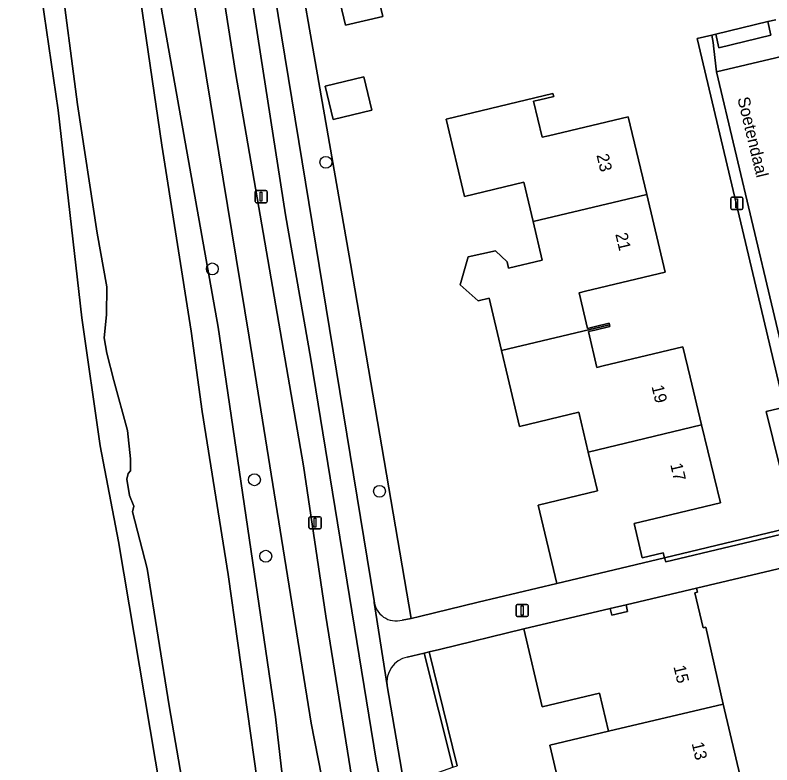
# Model space of a CAD drawing. Extents: x 157648 to 158502, y 379212 to 380938.
# Drawn here: x 158059.6 to 158121.9, y 380718.1 to 380779.8 of the extents above; entities that cross this region are included whole.
import ezdxf

# ---------------------------------------------------------------- set-up
doc = ezdxf.new("R2010")
doc.units = 0
for name, color, linetype in [('IMGEO_Berm_groen', 7, 'Continuous'), ('IMGEO_Boom', 7, 'Continuous'), ('IMGEO_Erf', 7, 'Continuous'), ('IMGEO_Fietspad_gesloten', 7, 'Continuous'), ('IMGEO_Groenvoorziening', 7, 'Continuous'), ('IMGEO_Haag', 7, 'Continuous'), ('IMGEO_Hek', 7, 'Continuous'), ('IMGEO_Lichtmast', 7, 'Continuous'), ('IMGEO_Muur', 7, 'Continuous'), ('IMGEO_Oever', 7, 'Continuous'), ('IMGEO_Openbare_ruimte_label', 7, 'Continuous'), ('IMGEO_Pand', 7, 'Continuous'), ('IMGEO_Pand_nummerreeks', 7, 'Continuous'), ('IMGEO_Pand_overbouw', 7, 'Continuous'), ('IMGEO_Rijbaan_lokaal_open', 7, 'Continuous'), ('IMGEO_Voetpad_open', 7, 'Continuous'), ('IMGEO_Waterloop', 7, 'Continuous')]:
    doc.layers.add(name, color=color, linetype=linetype)

msp = doc.modelspace()

# ---------------------------------------------------------------- linework, layer by layer
at = {"layer": 'IMGEO_Berm_groen'}
for points in [[(158074.722, 380845.281), (158073.77, 380825.588), (158073.53, 380817.736), (158073.74, 380808.222), (158074.257, 380799.995), (158075.149, 380791.663), (158077.752, 380775.038), (158083.324, 380742.71), (158085.161, 380730.364), (158087.771, 380714.145)], [(158086.247, 380709.967), (158083.967, 380721.558), (158078.875, 380753.293), (158072.85, 380789.952), (158072.183, 380797.022), (158071.547, 380810.292), (158071.664, 380824.995), (158072.408, 380844.132)], [(158090.58, 380712.063), (158089.326, 380718.53), (158083.93, 380751.483), (158081.843, 380763.329), (158076.731, 380796.337), (158076.033, 380804.062), (158075.551, 380812.413), (158075.894, 380824.951), (158076.565, 380843.437)], [(158072.443, 380710.798), (158068.133, 380736.496), (158066.607, 380744.346), (158065.118, 380754.866), (158063.151, 380771.932), (158061.06, 380786.446), (158059.17, 380797.604), (158058.451, 380809.187), (158058.445, 380817.028), (158058.623, 380823.199), (158058.845, 380827.656), (158058.831, 380835.186)], [(158069.5, 380835.023), (158068.853, 380822.132), (158068.821, 380815.256), (158068.663, 380810.855), (158070.02, 380791.954), (158071.648, 380780.25), (158076.307, 380754.118), (158081.044, 380722.078), (158082.383, 380710.401)]]:
    msp.add_lwpolyline(points, dxfattribs=at)
at = {"layer": 'IMGEO_Boom'}
for centre in [(158085.176, 380767.66), (158075.839, 380758.898), (158079.299, 380741.564), (158089.587, 380740.618), (158080.23, 380735.282)]:
    msp.add_circle(centre, 0.489, dxfattribs=at)
at = {"layer": 'IMGEO_Erf'}
for points in [[(158080.044, 380800.241), (158087.197, 380759.348), (158092.188, 380730.175), (158092.867, 380730.337), (158097.707, 380731.493), (158104.177, 380733.037), (158102.634, 380739.486), (158107.513, 380740.652), (158106.751, 380743.841), (158105.969, 380747.11), (158101.109, 380745.948), (158100.145, 380750), (158099.626, 380752.18), (158098.6, 380756.49), (158097.706, 380756.278), (158096.222, 380757.584), (158096.875, 380759.9), (158099.132, 380760.375), (158100.082, 380759.485), (158100.21, 380758.947), (158102.978, 380759.607), (158102.22, 380762.786), (158101.449, 380766.018), (158096.573, 380764.855), (158095.057, 380771.215), (158103.855, 380773.313), (158103.913, 380773.074), (158102.782, 380772.805), (158102.257, 380772.68), (158102.964, 380769.713), (158103.489, 380769.838), (158110.045, 380771.401), (158111.568, 380765.015), (158113.091, 380758.628), (158106.535, 380757.065), (158106.003, 380756.938), (158106.702, 380754.008), (158107.229, 380754.133), (158108.464, 380754.425), (158108.496, 380754.291), (158108.528, 380754.153), (158107.292, 380753.863), (158106.766, 380753.74), (158107.466, 380750.804), (158107.987, 380750.928), (158114.543, 380752.492), (158115.14, 380750), (158116.08, 380746.077), (158117.618, 380739.664), (158112.25, 380738.38), (158110.519, 380737.966), (158111.194, 380735.148), (158112.925, 380735.562), (158113.022, 380735.153), (158123.627, 380737.695)], [(158088.703, 380784.527), (158089.865, 380779.654), (158086.779, 380778.918), (158083.38, 380793.171)], [(158122.473, 380742.741), (158121.378, 380747.181), (158122.889, 380747.526), (158115.723, 380777.83), (158116.916, 380778.105), (158117.151, 380778.162), (158117.252, 380778.186), (158121.537, 380779.221), (158122.178, 380779.376)], [(158124.335, 380734.713), (158115.666, 380732.643), (158115.745, 380732.331), (158115.527, 380732.276), (158116.193, 380729.392), (158116.412, 380729.442), (158117.857, 380723.129), (158119.37, 380716.746)], [(158104.349, 380716.606), (158103.603, 380719.753), (158108.424, 380720.896), (158107.68, 380724.034), (158102.958, 380722.915), (158101.459, 380729.318), (158094.514, 380727.615), (158093.659, 380727.413), (158095.985, 380718.066)]]:
    msp.add_lwpolyline(points, dxfattribs=at)
for points in [[(158088.958, 380771.931), (158085.782, 380771.173), (158085.127, 380773.919), (158088.303, 380774.677)], [(158108.564, 380730.981), (158108.691, 380730.436), (158109.984, 380730.736), (158109.886, 380731.287)]]:
    msp.add_lwpolyline(points, close=True, dxfattribs=at)
at = {"layer": 'IMGEO_Fietspad_gesloten'}
for points in [[(158101.997, 380686.517), (158099.225, 380689.283), (158096.253, 380693.04), (158093.82, 380696.7), (158091.576, 380701.56), (158090.275, 380703.817), (158089.886, 380705.995), (158088.632, 380709.876), (158087.771, 380714.145), (158085.161, 380730.364), (158083.324, 380742.71), (158077.752, 380775.038), (158075.149, 380791.663), (158074.257, 380799.995), (158073.74, 380808.222), (158073.53, 380817.736), (158073.77, 380825.588), (158074.722, 380845.281)], [(158072.408, 380844.132), (158071.664, 380824.995), (158071.547, 380810.292), (158072.183, 380797.022), (158072.85, 380789.952), (158078.875, 380753.293), (158083.967, 380721.558), (158086.247, 380709.967), (158087.828, 380704.378), (158089.981, 380698.857), (158092.702, 380693.486), (158095.812, 380689.406), (158098.383, 380686.287), (158098.814, 380685.85), (158101.015, 380683.621), (158106.429, 380678.739), (158108.403, 380676.982), (158109.59, 380678.488)]]:
    msp.add_lwpolyline(points, dxfattribs=at)
at = {"layer": 'IMGEO_Groenvoorziening'}
for points in [[(158091.453, 380730.031), (158092.188, 380730.175), (158087.197, 380759.348), (158080.044, 380800.241)], [(158078.428, 380797.97), (158080.395, 380784.926), (158089.136, 380731.609)], [(158090.219, 380724.615), (158091.565, 380716.813), (158094.466, 380717.531), (158095.606, 380717.933), (158093.27, 380727.321)], [(158093.27, 380727.321), (158091.859, 380726.987)]]:
    msp.add_lwpolyline(points, dxfattribs=at)
for points in [[(158121.537, 380779.221), (158117.252, 380778.186), (158117.502, 380777.074), (158121.758, 380778.099)], [(158123.705, 380737.354), (158123.627, 380737.695), (158113.022, 380735.153), (158113.137, 380734.808)], [(158093.659, 380727.413), (158093.27, 380727.321), (158095.606, 380717.933), (158095.985, 380718.066)]]:
    msp.add_lwpolyline(points, close=True, dxfattribs=at)
for centre, radius, start, end in [((158090.959, 380731.796), 1.833, 185.86424, 285.62188), ((158092.289, 380724.936), 2.095, 101.85512, 188.82494)]:
    msp.add_arc(centre, radius, start, end, dxfattribs=at)
at = {"layer": 'IMGEO_Haag'}
for points in [[(158121.537, 380779.221), (158117.252, 380778.186), (158117.502, 380777.074), (158121.758, 380778.099)], [(158123.705, 380737.354), (158123.627, 380737.695), (158113.022, 380735.153), (158113.137, 380734.808)], [(158093.659, 380727.413), (158093.27, 380727.321), (158095.606, 380717.933), (158095.985, 380718.066)]]:
    msp.add_lwpolyline(points, close=True, dxfattribs=at)
at = {"layer": 'IMGEO_Hek'}
for points in [[(158116.916, 380778.105), (158115.723, 380777.83)], [(158124.335, 380734.713), (158115.666, 380732.643)], [(158104.177, 380733.037), (158097.707, 380731.493)], [(158097.707, 380731.493), (158092.867, 380730.337)], [(158092.867, 380730.337), (158092.188, 380730.175)], [(158101.459, 380729.318), (158094.514, 380727.615)]]:
    msp.add_lwpolyline(points, dxfattribs=at)
at = {"layer": 'IMGEO_Lichtmast'}
for p, q in [((158079.352, 380764.441), (158079.352, 380765.241)), ((158079.352, 380765.241), (158079.352, 380764.441)), ((158079.452, 380765.341), (158080.242, 380765.341)), ((158080.242, 380765.341), (158079.452, 380765.341)), ((158080.342, 380765.241), (158080.342, 380764.441)), ((158080.342, 380764.441), (158080.342, 380765.241)), ((158080.242, 380764.341), (158079.452, 380764.341)), ((158079.452, 380764.341), (158080.242, 380764.341)), ((158118.469, 380763.886), (158118.469, 380764.686)), ((158118.469, 380764.686), (158118.469, 380763.886)), ((158118.569, 380764.786), (158119.359, 380764.786)), ((158119.359, 380764.786), (158118.569, 380764.786)), ((158119.459, 380764.686), (158119.459, 380763.886)), ((158119.459, 380763.886), (158119.459, 380764.686)), ((158119.359, 380763.786), (158118.569, 380763.786)), ((158118.569, 380763.786), (158119.359, 380763.786)), ((158083.789, 380737.631), (158083.789, 380738.431)), ((158083.789, 380738.431), (158083.789, 380737.631)), ((158083.889, 380738.531), (158084.679, 380738.531)), ((158084.679, 380738.531), (158083.889, 380738.531)), ((158084.779, 380738.431), (158084.779, 380737.631)), ((158084.779, 380737.631), (158084.779, 380738.431)), ((158084.679, 380737.531), (158083.889, 380737.531)), ((158083.889, 380737.531), (158084.679, 380737.531)), ((158100.819, 380730.42), (158100.819, 380731.22)), ((158100.819, 380731.22), (158100.819, 380730.42)), ((158100.919, 380731.32), (158101.709, 380731.32)), ((158101.709, 380731.32), (158100.919, 380731.32)), ((158101.809, 380731.22), (158101.809, 380730.42)), ((158101.809, 380730.42), (158101.809, 380731.22)), ((158101.709, 380730.32), (158100.919, 380730.32)), ((158100.919, 380730.32), (158101.709, 380730.32))]:
    msp.add_line(p, q, dxfattribs=at)
for points in [[(158079.772, 380765.216), (158079.922, 380765.216), (158079.922, 380764.466), (158079.772, 380764.466), (158079.772, 380765.216)], [(158118.889, 380764.661), (158119.039, 380764.661), (158119.039, 380763.911), (158118.889, 380763.911), (158118.889, 380764.661)], [(158084.209, 380738.406), (158084.359, 380738.406), (158084.359, 380737.656), (158084.209, 380737.656), (158084.209, 380738.406)], [(158101.239, 380731.195), (158101.389, 380731.195), (158101.389, 380730.445), (158101.239, 380730.445), (158101.239, 380731.195)]]:
    msp.add_lwpolyline(points, dxfattribs=at)
for centre, start, end in [((158079.452, 380765.241), 90, 180), ((158079.452, 380765.241), 90, 180), ((158080.242, 380765.241), 0, 90), ((158080.242, 380765.241), 360, 90), ((158079.452, 380764.441), 180, 270), ((158079.452, 380764.441), 180, 270), ((158080.242, 380764.441), 270, 0), ((158080.242, 380764.441), 270, 0), ((158118.569, 380764.686), 90, 180), ((158118.569, 380764.686), 90, 180), ((158119.359, 380764.686), 0, 90), ((158119.359, 380764.686), 360, 90), ((158118.569, 380763.886), 180, 270), ((158118.569, 380763.886), 180, 270), ((158119.359, 380763.886), 270, 0), ((158119.359, 380763.886), 270, 0), ((158083.889, 380738.431), 90, 180), ((158083.889, 380738.431), 90, 180), ((158084.679, 380738.431), 0, 90), ((158084.679, 380738.431), 360, 90), ((158083.889, 380737.631), 180, 270), ((158083.889, 380737.631), 180, 270), ((158084.679, 380737.631), 270, 0), ((158084.679, 380737.631), 270, 0), ((158100.919, 380731.22), 90, 180), ((158100.919, 380731.22), 90, 180), ((158101.709, 380731.22), 0, 90), ((158101.709, 380731.22), 360, 90), ((158100.919, 380730.42), 180, 270), ((158100.919, 380730.42), 180, 270), ((158101.709, 380730.42), 270, 0), ((158101.709, 380730.42), 270, 0)]:
    msp.add_arc(centre, 0.1, start, end, dxfattribs=at)
at = {"layer": 'IMGEO_Muur'}
msp.add_lwpolyline([(158080.044, 380800.241), (158087.197, 380759.348), (158092.188, 380730.175)], dxfattribs=at)
at = {"layer": 'IMGEO_Oever'}
for points in [[(158073.824, 380714.107), (158072.291, 380722.982), (158070.478, 380734.267), (158069.269, 380738.93), (158069.37, 380739.387), (158069.04, 380740.274), (158068.812, 380741.618), (158068.913, 380742.074), (158069.108, 380742.289), (158069.102, 380743.274), (158068.867, 380745.602), (158067.725, 380749.735), (158067.167, 380751.966), (158066.942, 380753.228), (158067.138, 380755.126), (158067.151, 380757.425), (158066.366, 380761.821), (158064.75, 380772.418), (158061.835, 380794.692), (158060.985, 380809.882), (158059.752, 380816.761), (158059.936, 380821.861), (158060.626, 380827.415), (158061.174, 380838.818)], [(158058.831, 380835.186), (158058.845, 380827.656), (158058.623, 380823.199), (158058.445, 380817.028), (158058.451, 380809.187), (158059.17, 380797.604), (158061.06, 380786.446), (158063.151, 380771.932), (158065.118, 380754.866), (158066.607, 380744.346), (158068.133, 380736.496), (158072.443, 380710.798)], [(158066.668, 380834.92), (158066.913, 380813.82), (158067.79, 380795.511), (158068.182, 380794.175), (158068.654, 380793.746), (158068.715, 380793.339), (158068.442, 380793.038), (158068.255, 380792.66), (158068.331, 380791.925), (158071.685, 380769.055), (158074.1, 380753.776), (158074.991, 380747.168), (158077.152, 380733.766), (158080.326, 380711.216)], [(158082.383, 380710.401), (158081.044, 380722.078), (158076.307, 380754.118), (158071.648, 380780.25), (158070.02, 380791.954), (158068.663, 380810.855), (158068.821, 380815.256), (158068.853, 380822.132), (158069.5, 380835.023)]]:
    msp.add_lwpolyline(points, dxfattribs=at)
at = {"layer": 'IMGEO_Pand'}
for points in [[(158089.674, 380794.672), (158083.38, 380793.171), (158086.779, 380778.918), (158089.865, 380779.654), (158088.703, 380784.527), (158091.912, 380785.292)], [(158088.958, 380771.931), (158088.303, 380774.677), (158085.127, 380773.919), (158085.782, 380771.173)], [(158102.22, 380762.786), (158111.568, 380765.015), (158110.045, 380771.401), (158103.489, 380769.838), (158102.964, 380769.713), (158102.257, 380772.68), (158102.782, 380772.805), (158103.913, 380773.074), (158103.855, 380773.313), (158095.057, 380771.215), (158096.573, 380764.855), (158101.449, 380766.018)], [(158099.626, 380752.18), (158108.496, 380754.291), (158108.464, 380754.425), (158107.229, 380754.133), (158106.702, 380754.008), (158106.003, 380756.938), (158106.535, 380757.065), (158113.091, 380758.628), (158111.568, 380765.015), (158102.22, 380762.786), (158102.978, 380759.607), (158100.21, 380758.947), (158100.082, 380759.485), (158099.132, 380760.375), (158096.875, 380759.9), (158096.222, 380757.584), (158097.706, 380756.278), (158098.6, 380756.49)], [(158099.626, 380752.18), (158100.145, 380750), (158101.109, 380745.948), (158105.969, 380747.11), (158106.751, 380743.841), (158116.08, 380746.077), (158115.14, 380750), (158114.543, 380752.492), (158107.987, 380750.928), (158107.466, 380750.804), (158106.766, 380753.74), (158107.292, 380753.863), (158108.528, 380754.153), (158108.496, 380754.291)], [(158116.08, 380746.077), (158106.751, 380743.841), (158107.513, 380740.652), (158102.634, 380739.486), (158104.177, 380733.037), (158113.022, 380735.153), (158112.925, 380735.562), (158111.194, 380735.148), (158110.519, 380737.966), (158112.25, 380738.38), (158117.618, 380739.664)], [(158108.424, 380720.896), (158117.857, 380723.129), (158116.412, 380729.442), (158116.193, 380729.392), (158115.527, 380732.276), (158115.745, 380732.331), (158115.666, 380732.643), (158109.886, 380731.287), (158109.984, 380730.736), (158108.691, 380730.436), (158108.564, 380730.981), (158101.459, 380729.318), (158102.958, 380722.915), (158107.68, 380724.034)], [(158108.424, 380720.896), (158103.603, 380719.753), (158104.349, 380716.606), (158106.039, 380717.007), (158106.805, 380713.772), (158109.966, 380714.52), (158119.37, 380716.746), (158117.857, 380723.129)]]:
    msp.add_lwpolyline(points, close=True, dxfattribs=at)
at = {"layer": 'IMGEO_Pand_overbouw'}
msp.add_lwpolyline([(158108.564, 380730.981), (158108.691, 380730.436), (158109.984, 380730.736), (158109.886, 380731.287)], close=True, dxfattribs=at)
at = {"layer": 'IMGEO_Rijbaan_lokaal_open'}
msp.add_lwpolyline([(158127.067, 380777.387), (158117.291, 380775.089), (158124.841, 380743.309)], dxfattribs=at)
at = {"layer": 'IMGEO_Voetpad_open'}
for points in [[(158076.51, 380862.37), (158077.768, 380861.65), (158077.399, 380854.931), (158076.565, 380843.437), (158075.894, 380824.951), (158075.551, 380812.413), (158076.033, 380804.062), (158076.731, 380796.337), (158081.843, 380763.329), (158083.93, 380751.483), (158089.326, 380718.53), (158090.58, 380712.063), (158092.023, 380705.933), (158092.55, 380703.495), (158098.681, 380695.497), (158101.641, 380691.985), (158104.362, 380689.226), (158105.069, 380688.507), (158109.599, 380684.387), (158119.145, 380675.855), (158125.04, 380670.586), (158126.662, 380669.169), (158154.475, 380644.521), (158157.286, 380642.031)], [(158092.605, 380710.783), (158091.565, 380716.813), (158090.219, 380724.615), (158090.209, 380724.654), (158089.147, 380731.464), (158089.136, 380731.609), (158080.395, 380784.926), (158078.428, 380797.97)], [(158122.178, 380779.376), (158121.537, 380779.221), (158121.758, 380778.099), (158117.502, 380777.074), (158117.252, 380778.186), (158117.151, 380778.162), (158116.916, 380778.105), (158117.026, 380777.499), (158117.084, 380776.973), (158117.291, 380775.089), (158127.067, 380777.387)], [(158115.666, 380732.643), (158124.335, 380734.713), (158123.705, 380737.354), (158113.137, 380734.808), (158113.022, 380735.153), (158104.177, 380733.037), (158097.707, 380731.493), (158092.867, 380730.337), (158092.188, 380730.175), (158091.453, 380730.031)], [(158091.859, 380726.987), (158093.27, 380727.321), (158093.659, 380727.413), (158094.514, 380727.615), (158101.459, 380729.318), (158108.564, 380730.981), (158109.886, 380731.287), (158115.666, 380732.643)], [(158089.136, 380731.609), (158089.147, 380731.464), (158090.209, 380724.654), (158090.219, 380724.615)]]:
    msp.add_lwpolyline(points, dxfattribs=at)
msp.add_lwpolyline([(158117.291, 380775.089), (158117.084, 380776.973), (158117.026, 380777.499), (158116.916, 380778.105), (158115.723, 380777.83), (158122.889, 380747.526), (158121.378, 380747.181), (158122.473, 380742.741), (158124.841, 380743.309)], close=True, dxfattribs=at)
for centre, radius, start, end in [((158090.959, 380731.796), 1.833, 185.86424, 285.62188), ((158092.289, 380724.936), 2.095, 101.85512, 188.82494)]:
    msp.add_arc(centre, radius, start, end, dxfattribs=at)
at = {"layer": 'IMGEO_Waterloop'}
for points in [[(158061.174, 380838.818), (158060.626, 380827.415), (158059.936, 380821.861), (158059.752, 380816.761), (158060.985, 380809.882), (158061.835, 380794.692), (158064.75, 380772.418), (158066.366, 380761.821), (158067.151, 380757.425), (158067.138, 380755.126), (158066.942, 380753.228), (158067.167, 380751.966), (158067.725, 380749.735), (158068.867, 380745.602), (158069.102, 380743.274), (158069.108, 380742.289), (158068.913, 380742.074), (158068.812, 380741.618), (158069.04, 380740.274), (158069.37, 380739.387), (158069.269, 380738.93), (158070.478, 380734.267), (158072.291, 380722.982), (158073.824, 380714.107)], [(158080.326, 380711.216), (158077.152, 380733.766), (158074.991, 380747.168), (158074.1, 380753.776), (158071.685, 380769.055), (158068.331, 380791.925), (158068.255, 380792.66), (158068.442, 380793.038), (158068.715, 380793.339), (158068.654, 380793.746), (158068.182, 380794.175), (158067.79, 380795.511), (158066.913, 380813.82), (158066.668, 380834.92)]]:
    msp.add_lwpolyline(points, dxfattribs=at)

# ---------------------------------------------------------------- texts
at = {"layer": 'IMGEO_Openbare_ruimte_label'}
msp.add_text('Soetendaal', height=1, rotation=283.64724, dxfattribs=at).set_placement((158119.014, 380772.909))
at = {"layer": 'IMGEO_Pand_nummerreeks'}
for s, rotation, p in [('23', 283.41291, (158107.425, 380768.25)), ('21', 283.41291, (158108.974, 380761.754)), ('19', 283.47815, (158111.951, 380749.235)), ('17', 283.48189, (158113.488, 380742.821)), ('15', 283.33614, (158113.756, 380726.207)), ('13', 283.33614, (158115.252, 380719.896))]:
    msp.add_text(s, height=1, rotation=rotation, dxfattribs=at).set_placement(p)

doc.saveas('drawing.dxf')
